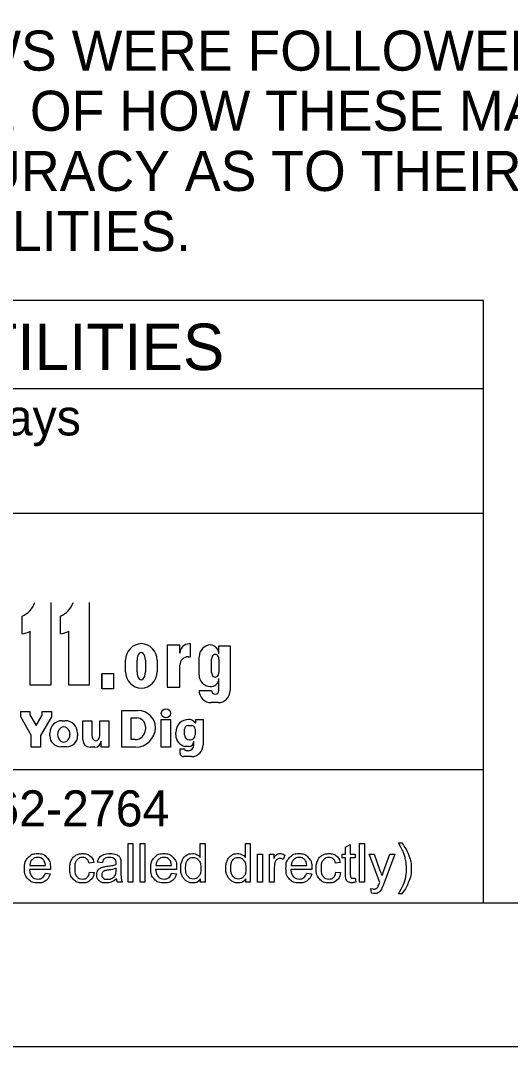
# Model space of a CAD drawing. Extents: x 0 to 34, y 0 to 22.
# Drawn here: x 4.294 to 6.004, y 0 to 3.581 of the extents above; entities that cross this region are included whole.
import ezdxf

# ---------------------------------------------------------------- set-up
doc = ezdxf.new("R2010")
doc.units = 0
for name, color, linetype in [('SH_Border', 7, 'Continuous'), ('SH_Cut_Line', 7, 'Continuous'), ('SH_Data', 7, 'Continuous'), ('SH_Text', 7, 'Continuous')]:
    doc.layers.add(name, color=color, linetype=linetype)

msp = doc.modelspace()

# ---------------------------------------------------------------- linework, layer by layer
at = {"layer": 'SH_Border'}
msp.add_lwpolyline([(1.5, 21.5), (33.5, 21.5), (33.5, 0.5), (1.5, 0.5)], close=True, dxfattribs=at)
at = {"layer": 'SH_Cut_Line'}
msp.add_lwpolyline([(0, 0), (34, 0), (34, 22), (0, 22)], close=True, dxfattribs=at)
at = {"layer": 'SH_Data'}
for p, q in [((5.9103, 2.6037), (2.0853, 2.6037)), ((5.9103, 0.5), (5.9103, 2.6037)), ((2.0853, 2.2963), (5.9103, 2.2963)), ((2.0853, 1.8613), (5.9103, 1.8613)), ((5.9103, 0.9661), (2.0853, 0.9661)), ((5.9103, 0.5), (2.0853, 0.5))]:
    msp.add_line(p, q, dxfattribs=at)
at = {"layer": 'SH_Text'}
for p, q in [((4.3993, 1.5493), (4.3993, 1.2613)), ((4.5333, 1.5493), (4.5333, 1.2613)), ((4.2989, 1.4407), (4.2989, 1.502)), ((4.4328, 1.4407), (4.4328, 1.502)), ((4.3279, 1.2613), (4.3279, 1.4491)), ((4.4619, 1.2613), (4.4619, 1.4491)), ((4.8499, 1.4007), (4.8059, 1.4007)), ((4.8059, 1.4007), (4.8059, 1.254)), ((4.8499, 1.3723), (4.8499, 1.4007)), ((4.8865, 1.4053), (4.8829, 1.4053)), ((4.8865, 1.3605), (4.8865, 1.4053)), ((4.9863, 1.37), (4.9863, 1.3979)), ((4.9863, 1.3979), (5.0255, 1.3979)), ((5.0255, 1.3979), (5.0255, 1.2423)), ((4.6601, 1.3079), (4.6601, 1.3487)), ((4.7006, 1.3072), (4.7006, 1.3487)), ((4.7296, 1.3487), (4.7296, 1.3072)), ((4.7701, 1.3487), (4.7701, 1.3079)), ((4.8499, 1.254), (4.8499, 1.3308)), ((4.8796, 1.3605), (4.8865, 1.3605)), ((4.917, 1.2976), (4.917, 1.3602)), ((4.9606, 1.3059), (4.9606, 1.3519)), ((4.9863, 1.3519), (4.9863, 1.3059)), ((4.5765, 1.3018), (4.5765, 1.2478)), ((4.3993, 1.2613), (4.3279, 1.2613)), ((4.5333, 1.2613), (4.4619, 1.2613)), ((4.8059, 1.254), (4.8499, 1.254)), ((4.9863, 1.2423), (4.9863, 1.284)), ((4.917, 1.2423), (4.9606, 1.2423)), ((4.9834, 1.2002), (4.9591, 1.2002)), ((4.2942, 1.1698), (4.3265, 1.1698)), ((4.2942, 1.1504), (4.2942, 1.1698)), ((4.3314, 1.0866), (4.2942, 1.1504)), ((4.3265, 1.1698), (4.3265, 1.1575)), ((4.3265, 1.1575), (4.3482, 1.1203)), ((4.3482, 1.1203), (4.3691, 1.1562)), ((4.4013, 1.1504), (4.3634, 1.0853)), ((4.3691, 1.1562), (4.3691, 1.1698)), ((4.3691, 1.1698), (4.4013, 1.1698)), ((4.4013, 1.1698), (4.4013, 1.1504)), ((4.6474, 1.173), (4.7035, 1.173)), ((4.6474, 1.0446), (4.6474, 1.173)), ((4.6798, 1.071), (4.6798, 1.1466)), ((4.6798, 1.1466), (4.7, 1.1466)), ((4.4388, 1.1372), (4.4497, 1.1372)), ((4.5109, 1.1372), (4.5422, 1.1372)), ((4.5109, 1.0701), (4.5109, 1.1372)), ((4.5422, 1.1372), (4.5422, 1.0874)), ((4.5705, 1.0859), (4.5705, 1.1372)), ((4.5705, 1.1372), (4.6017, 1.1372)), ((4.6017, 1.1372), (4.6017, 1.0446)), ((4.7294, 1.1173), (4.7294, 1.1066)), ((4.7848, 1.1409), (4.8168, 1.1409)), ((4.7848, 1.0446), (4.7848, 1.1409)), ((4.8168, 1.1409), (4.8168, 1.0446)), ((4.879, 1.1202), (4.8904, 1.1202)), ((4.8974, 1.1359), (4.9051, 1.1299)), ((4.9051, 1.1412), (4.931, 1.1412)), ((4.9051, 1.1299), (4.9051, 1.1412)), ((4.9051, 1.1412), (4.931, 1.1412)), ((4.931, 1.1412), (4.931, 1.0525)), ((4.3314, 1.0446), (4.3314, 1.0866)), ((4.3634, 1.0853), (4.3634, 1.0446)), ((4.3958, 1.0844), (4.3958, 1.0941)), ((4.4928, 1.0941), (4.4928, 1.0844)), ((4.8357, 1.0873), (4.8357, 1.0963)), ((4.8658, 1.088), (4.8658, 1.1071)), ((4.9036, 1.1071), (4.9036, 1.088)), ((4.3634, 1.0446), (4.3314, 1.0446)), ((4.4543, 1.0459), (4.4343, 1.0459)), ((4.5534, 1.0446), (4.5365, 1.0446)), ((4.575, 1.0446), (4.575, 1.0662)), ((4.6017, 1.0446), (4.575, 1.0446)), ((4.6956, 1.0446), (4.6474, 1.0446)), ((4.6938, 1.071), (4.6798, 1.071)), ((4.8168, 1.0446), (4.7848, 1.0446)), ((4.8505, 1.0235), (4.8505, 1.0389)), ((4.8505, 1.0389), (4.8658, 1.0389)), ((4.8807, 1.047), (4.8684, 1.047)), ((4.8862, 1.0706), (4.8832, 1.0706)), ((4.899, 1.0516), (4.899, 1.0655)), ((4.8903, 1.0118), (4.8623, 1.0118)), ((4.8719, 1.0326), (4.8799, 1.0326))]:
    msp.add_line(p, q, dxfattribs=at)
msp.add_lwpolyline([(4.5787, 1.3018), (4.6184, 1.3018), (4.6184, 1.2478), (4.5787, 1.2478)], close=True, dxfattribs=at)
for points in [[(4.6697, 0.573), (4.6697, 0.7082), (4.6862, 0.7082), (4.6862, 0.573), (4.6697, 0.573)], [(4.7116, 0.573), (4.7116, 0.7082), (4.7282, 0.7082), (4.7282, 0.573), (4.7116, 0.573)], [(4.9212, 0.6597), (4.9212, 0.7082), (4.9378, 0.7082), (4.9378, 0.573), (4.9224, 0.573)], [(5.0786, 0.6597), (5.0786, 0.7082), (5.0951, 0.7082), (5.0951, 0.573), (5.0798, 0.573)], [(5.4284, 0.6017), (5.4284, 0.6581), (5.4161, 0.6581), (5.4161, 0.671), (5.4284, 0.671), (5.4284, 0.6952), (5.4449, 0.7052), (5.4449, 0.671), (5.4615, 0.671), (5.4615, 0.6581), (5.4449, 0.6581), (5.4449, 0.6007)], [(5.4774, 0.573), (5.4774, 0.7082), (5.494, 0.7082), (5.494, 0.573), (5.4774, 0.573)], [(5.6131, 0.7104), (5.625, 0.7104)], [(5.1213, 0.573), (5.1213, 0.671), (5.1379, 0.671), (5.1379, 0.573), (5.1213, 0.573)], [(5.1629, 0.573), (5.1629, 0.671), (5.1779, 0.671), (5.1779, 0.6561)], [(5.2161, 0.6678), (5.2103, 0.6525)], [(5.5474, 0.5729), (5.5102, 0.671), (5.5281, 0.671), (5.5485, 0.6144)], [(5.5624, 0.6139), (5.5834, 0.671), (5.6, 0.671), (5.5628, 0.5713)], [(4.3979, 0.6177), (4.3248, 0.6177)], [(4.3257, 0.6313), (4.3804, 0.6313)], [(4.5494, 0.6421), (4.5332, 0.6397)], [(4.5346, 0.6089), (4.5509, 0.6067)], [(4.5786, 0.6408), (4.5623, 0.643)], [(4.6275, 0.6161), (4.6276, 0.6221)], [(4.6443, 0.6362), (4.6443, 0.6141)], [(4.8385, 0.6177), (4.7654, 0.6177)], [(4.7664, 0.6313), (4.8211, 0.6313)], [(5.1795, 0.6243), (5.1795, 0.573), (5.1629, 0.573)], [(5.3105, 0.6177), (5.2375, 0.6177)], [(5.2384, 0.6313), (5.2931, 0.6313)], [(5.4096, 0.6421), (5.3934, 0.6397)], [(5.3949, 0.6089), (5.4112, 0.6067)], [(4.3803, 0.6046), (4.3974, 0.6025)], [(4.6496, 0.573), (4.6323, 0.573)], [(4.8209, 0.6046), (4.838, 0.6025)], [(4.9224, 0.573), (4.9224, 0.5854)], [(5.0798, 0.573), (5.0798, 0.5854)], [(5.2929, 0.6046), (5.3101, 0.6025)], [(5.4615, 0.5878), (5.4639, 0.5732)], [(5.519, 0.5354), (5.5171, 0.551)], [(5.625, 0.5333), (5.6131, 0.5333)]]:
    msp.add_lwpolyline(points, dxfattribs=at)
msp.add_circle((4.8012, 1.1628), 0.016, dxfattribs=at)
for centre, radius, start, end in [((4.2683, 1.5756), 0.0796, 292.5572, 340.7355), ((4.4023, 1.5756), 0.0796, 292.5572, 340.7355), ((4.2917, 1.52), 0.0796, 275.1733, 297.0931), ((4.4256, 1.52), 0.0796, 275.1733, 297.0931), ((4.7177, 1.3487), 0.0576, 92.5886, 180), ((4.7125, 1.3487), 0.0576, 0, 87.4114), ((4.8829, 1.3723), 0.033, 90, 180), ((4.9584, 1.3602), 0.0413, 92.6865, 180), ((4.9547, 1.37), 0.0316, 0, 86.9262), ((4.8796, 1.3308), 0.0297, 90, 180), ((4.7177, 1.3079), 0.0576, 180, 267.4114), ((4.7125, 1.3079), 0.0576, 272.5886, 0), ((4.9587, 1.2976), 0.0417, 180, 265.7132), ((4.9582, 1.284), 0.0281, 264.7825, 0), ((4.9591, 1.2423), 0.0421, 180, 270), ((4.9834, 1.2423), 0.0421, 270, 0), ((4.7, 1.1173), 0.0294, 0, 90), ((4.7035, 1.1116), 0.0614, 0.9944, 90), ((4.4388, 1.0941), 0.043, 90, 180), ((4.4497, 1.0941), 0.043, 0, 90), ((4.6956, 1.1138), 0.0692, 270, 359.0635), ((4.8806, 1.0963), 0.0449, 89.0934, 180), ((4.879, 1.1071), 0.0132, 90, 180), ((4.8818, 1.1158), 0.0254, 52.1415, 91.2046), ((4.8904, 1.1071), 0.0132, 0, 90), ((4.4343, 1.0844), 0.0385, 180, 270), ((4.4543, 1.0844), 0.0385, 270, 0), ((4.6938, 1.1066), 0.0356, 270, 0), ((4.8767, 1.0873), 0.0411, 180, 258.2203), ((4.8832, 1.088), 0.0174, 180, 270), ((4.8862, 1.088), 0.0174, 270, 0), ((4.5365, 1.0701), 0.0255, 180, 270), ((4.5534, 1.0662), 0.0216, 270, 0), ((4.8719, 1.0387), 0.00614, 180, 270), ((4.8799, 1.0516), 0.0191, 270, 0), ((4.8807, 1.0653), 0.0183, 270, 0), ((4.8903, 1.0525), 0.0408, 270, 0), ((4.8623, 1.0235), 0.0118, 180, 270)]:
    msp.add_arc(centre, radius, start, end, dxfattribs=at)
for centre, major_axis, ratio, start_param, end_param in [((4.7151, 1.3487), (0, 0.0262), 0.553236, 4.712389, 7.853982), ((4.9734, 1.3519), (0, 0.0166), 0.777179, 4.712389, 7.853982), ((4.7151, 1.3072), (0, 0.0277), 0.522014, 1.570796, 4.712389), ((4.9734, 1.3059), (0, 0.0166), 0.777179, 1.570796, 4.712389), ((4.9734, 1.2423), (0.0129, 0), 0.959012, 3.141593, 6.283185), ((4.4447, 1.0893), (0, 0.0261), 0.832186, 4.712389, 7.853982), ((4.4447, 1.0893), (0, 0.0272), 0.797287, 1.570796, 4.712389), ((4.5563, 1.088), (-0.001, 0.0208), 0.679042, 1.570796, 4.575961)]:
    msp.add_ellipse(centre, major_axis=major_axis, ratio=ratio, start_param=start_param, end_param=end_param, dxfattribs=at)
for points, degree in [([(5.6131, 0.5333), (5.6406, 0.5775), (5.6406, 0.6218), (5.6406, 0.6392), (5.6367, 0.6562), (5.6336, 0.67), (5.6279, 0.6828), (5.6244, 0.6911), (5.6131, 0.7104)], 3), ([(5.625, 0.7104), (5.6423, 0.6873), (5.6506, 0.664), (5.6577, 0.6439), (5.6577, 0.6219), (5.6577, 0.597), (5.6482, 0.5738), (5.6386, 0.5506), (5.625, 0.5333)], 3), ([(4.3974, 0.6025), (4.3933, 0.5874), (4.3824, 0.5792), (4.3714, 0.5709), (4.3544, 0.5709), (4.3329, 0.5709), (4.3203, 0.5841), (4.3077, 0.5973), (4.3077, 0.6212), (4.3077, 0.6459), (4.3204, 0.6595), (4.3332, 0.6731), (4.3534, 0.6731), (4.3731, 0.6731), (4.3855, 0.6598), (4.3979, 0.6464), (4.3979, 0.6221), (4.3979, 0.6207), (4.3979, 0.6177)], 3), ([(4.3804, 0.6313), (4.3793, 0.6437), (4.3742, 0.6499), (4.3662, 0.6595), (4.3536, 0.6595), (4.3422, 0.6595), (4.3344, 0.6519), (4.3266, 0.6442), (4.3257, 0.6313)], 3), ([(4.5509, 0.6067), (4.5482, 0.5899), (4.5372, 0.5804), (4.5262, 0.5709), (4.5101, 0.5709), (4.49, 0.5709), (4.4778, 0.584), (4.4656, 0.5971), (4.4656, 0.6216), (4.4656, 0.6375), (4.4709, 0.6494), (4.4761, 0.6612), (4.4869, 0.6672), (4.4976, 0.6731), (4.5103, 0.6731), (4.5262, 0.6731), (4.5364, 0.6651), (4.5465, 0.657), (4.5494, 0.6421)], 3), ([(4.5332, 0.6397), (4.5309, 0.6496), (4.525, 0.6545), (4.5192, 0.6595), (4.5109, 0.6595), (4.4984, 0.6595), (4.4905, 0.6505), (4.4827, 0.6416), (4.4827, 0.6221), (4.4827, 0.6023), (4.4903, 0.5934), (4.4978, 0.5845), (4.51, 0.5845), (4.5198, 0.5845), (4.5263, 0.5904), (4.5329, 0.5964), (4.5346, 0.6089)], 3), ([(4.629, 0.5851), (4.6197, 0.5773), (4.6112, 0.5741), (4.6027, 0.5709), (4.5929, 0.5709), (4.5768, 0.5709), (4.5681, 0.5787), (4.5595, 0.5866), (4.5595, 0.5988), (4.5595, 0.606), (4.5627, 0.612), (4.566, 0.6179), (4.5713, 0.6215), (4.5766, 0.6251), (4.5832, 0.6269), (4.5881, 0.6282), (4.598, 0.6294), (4.6181, 0.6318), (4.6275, 0.6351), (4.6276, 0.6385), (4.6276, 0.6395), (4.6276, 0.6496), (4.6229, 0.6538), (4.6166, 0.6594), (4.6041, 0.6594), (4.5924, 0.6594), (4.5868, 0.6553), (4.5813, 0.6512), (4.5786, 0.6408)], 3), ([(4.5623, 0.643), (4.5645, 0.6534), (4.5696, 0.6598), (4.5747, 0.6662), (4.5843, 0.6697), (4.5938, 0.6731), (4.6065, 0.6731), (4.619, 0.6731), (4.6268, 0.6702), (4.6346, 0.6672), (4.6383, 0.6628), (4.642, 0.6583), (4.6435, 0.6515), (4.6443, 0.6472), (4.6443, 0.6362)], 3), ([(4.838, 0.6025), (4.834, 0.5874), (4.823, 0.5792), (4.812, 0.5709), (4.795, 0.5709), (4.7735, 0.5709), (4.7609, 0.5841), (4.7484, 0.5973), (4.7484, 0.6212), (4.7484, 0.6459), (4.7611, 0.6595), (4.7738, 0.6731), (4.7941, 0.6731), (4.8137, 0.6731), (4.8261, 0.6598), (4.8386, 0.6464), (4.8386, 0.6221), (4.8386, 0.6207), (4.8385, 0.6177)], 3), ([(4.8211, 0.6313), (4.82, 0.6437), (4.8148, 0.6499), (4.8069, 0.6595), (4.7942, 0.6595), (4.7828, 0.6595), (4.775, 0.6519), (4.7672, 0.6442), (4.7664, 0.6313)], 3), ([(4.9224, 0.5854), (4.9131, 0.5709), (4.895, 0.5709), (4.8833, 0.5709), (4.8735, 0.5773), (4.8637, 0.5838), (4.8583, 0.5953), (4.8529, 0.6069), (4.8529, 0.6219), (4.8529, 0.6366), (4.8578, 0.6485), (4.8627, 0.6604), (4.8724, 0.6668), (4.8822, 0.6731), (4.8942, 0.6731), (4.9031, 0.6731), (4.91, 0.6694), (4.9169, 0.6657), (4.9212, 0.6597)], 3), ([(4.87, 0.6219), (4.87, 0.6031), (4.8779, 0.5938), (4.8858, 0.5845), (4.8966, 0.5845), (4.9075, 0.5845), (4.9151, 0.5934), (4.9227, 0.6023), (4.9227, 0.6205), (4.9227, 0.6406), (4.915, 0.65), (4.9072, 0.6594), (4.8959, 0.6594), (4.8848, 0.6594), (4.8774, 0.6504), (4.87, 0.6414), (4.87, 0.6219)], 3), ([(5.0798, 0.5854), (5.0705, 0.5709), (5.0524, 0.5709), (5.0407, 0.5709), (5.0309, 0.5773), (5.0211, 0.5838), (5.0157, 0.5953), (5.0103, 0.6069), (5.0103, 0.6219), (5.0103, 0.6366), (5.0152, 0.6485), (5.02, 0.6604), (5.0298, 0.6668), (5.0395, 0.6731), (5.0516, 0.6731), (5.0604, 0.6731), (5.0673, 0.6694), (5.0742, 0.6657), (5.0786, 0.6597)], 3), ([(5.0274, 0.6219), (5.0274, 0.6031), (5.0353, 0.5938), (5.0432, 0.5845), (5.054, 0.5845), (5.0649, 0.5845), (5.0725, 0.5934), (5.0801, 0.6023), (5.0801, 0.6205), (5.0801, 0.6406), (5.0724, 0.65), (5.0646, 0.6594), (5.0533, 0.6594), (5.0422, 0.6594), (5.0348, 0.6504), (5.0274, 0.6414), (5.0274, 0.6219)], 3), ([(5.1779, 0.6561), (5.1836, 0.6665), (5.1884, 0.6698), (5.1932, 0.6731), (5.199, 0.6731), (5.2074, 0.6731), (5.2161, 0.6678)], 3), ([(5.2103, 0.6525), (5.2042, 0.656), (5.1981, 0.656), (5.1927, 0.656), (5.1884, 0.6528), (5.1841, 0.6495), (5.1823, 0.6437), (5.1795, 0.6348), (5.1795, 0.6243)], 3), ([(5.3101, 0.6025), (5.306, 0.5874), (5.295, 0.5792), (5.2841, 0.5709), (5.267, 0.5709), (5.2456, 0.5709), (5.233, 0.5841), (5.2204, 0.5973), (5.2204, 0.6212), (5.2204, 0.6459), (5.2331, 0.6595), (5.2458, 0.6731), (5.2661, 0.6731), (5.2857, 0.6731), (5.2982, 0.6598), (5.3106, 0.6464), (5.3106, 0.6221), (5.3106, 0.6207), (5.3105, 0.6177)], 3), ([(5.2931, 0.6313), (5.292, 0.6437), (5.2868, 0.6499), (5.2789, 0.6595), (5.2663, 0.6595), (5.2548, 0.6595), (5.247, 0.6519), (5.2393, 0.6442), (5.2384, 0.6313)], 3), ([(5.4112, 0.6067), (5.4085, 0.5899), (5.3975, 0.5804), (5.3864, 0.5709), (5.3704, 0.5709), (5.3503, 0.5709), (5.3381, 0.584), (5.3259, 0.5971), (5.3259, 0.6216), (5.3259, 0.6375), (5.3311, 0.6494), (5.3364, 0.6612), (5.3471, 0.6672), (5.3579, 0.6731), (5.3705, 0.6731), (5.3865, 0.6731), (5.3966, 0.6651), (5.4067, 0.657), (5.4096, 0.6421)], 3), ([(5.3934, 0.6397), (5.3911, 0.6496), (5.3853, 0.6545), (5.3794, 0.6595), (5.3711, 0.6595), (5.3586, 0.6595), (5.3508, 0.6505), (5.343, 0.6416), (5.343, 0.6221), (5.343, 0.6023), (5.3505, 0.5934), (5.3581, 0.5845), (5.3703, 0.5845), (5.38, 0.5845), (5.3866, 0.5904), (5.3931, 0.5964), (5.3949, 0.6089)], 3), ([(4.3248, 0.6177), (4.3257, 0.6016), (4.3339, 0.593), (4.3422, 0.5845), (4.3544, 0.5845), (4.3636, 0.5845), (4.37, 0.5893), (4.3765, 0.5941), (4.3803, 0.6046)], 3), ([(4.6276, 0.6221), (4.6186, 0.6185), (4.6005, 0.6159), (4.5903, 0.6144), (4.586, 0.6126), (4.5818, 0.6107), (4.5795, 0.6072), (4.5772, 0.6036), (4.5772, 0.5993), (4.5772, 0.5927), (4.5822, 0.5883), (4.5872, 0.5838), (4.5969, 0.5838), (4.6065, 0.5838), (4.6139, 0.588), (4.6214, 0.5922), (4.6249, 0.5995), (4.6275, 0.6051), (4.6275, 0.6161)], 3), ([(4.6443, 0.6141), (4.6443, 0.5909), (4.6454, 0.5848), (4.6464, 0.5787), (4.6496, 0.573)], 3), ([(4.7654, 0.6177), (4.7664, 0.6016), (4.7746, 0.593), (4.7828, 0.5845), (4.7951, 0.5845), (4.8042, 0.5845), (4.8106, 0.5893), (4.8171, 0.5941), (4.8209, 0.6046)], 3), ([(5.2375, 0.6177), (5.2384, 0.6016), (5.2466, 0.593), (5.2548, 0.5845), (5.2671, 0.5845), (5.2762, 0.5845), (5.2827, 0.5893), (5.2891, 0.5941), (5.2929, 0.6046)], 3), ([(5.5485, 0.6144), (5.5524, 0.6037), (5.5556, 0.5918), (5.5585, 0.603), (5.5624, 0.6139)], 3), ([(4.6323, 0.573), (4.6297, 0.5782), (4.629, 0.5851)], 2), ([(5.4639, 0.5732), (5.4569, 0.5717), (5.4514, 0.5717), (5.4423, 0.5717), (5.4374, 0.5745), (5.4324, 0.5774), (5.4304, 0.5821), (5.4284, 0.5867), (5.4284, 0.6017)], 3), ([(5.4449, 0.6007), (5.4449, 0.5936), (5.4458, 0.5916), (5.4467, 0.5895), (5.4486, 0.5883), (5.4506, 0.5871), (5.4543, 0.5871), (5.457, 0.5871), (5.4615, 0.5878)], 3), ([(5.5171, 0.551), (5.5226, 0.5495), (5.5266, 0.5495), (5.5321, 0.5495), (5.5355, 0.5514), (5.5388, 0.5532), (5.5409, 0.5565), (5.5424, 0.559), (5.5459, 0.5689), (5.5464, 0.5703), (5.5474, 0.5729)], 3), ([(5.5628, 0.5713), (5.5568, 0.5552), (5.5535, 0.5492), (5.5491, 0.541), (5.5433, 0.5372), (5.5376, 0.5334), (5.5297, 0.5334), (5.5249, 0.5334), (5.519, 0.5354)], 3)]:
    msp.add_open_spline(points, degree=degree, dxfattribs=at)

# ---------------------------------------------------------------- texts
at = {"layer": 'SH_Data'}
for s, p in [('DAMAGE PREVENTION LAWS WERE FOLLOWED AND THERE IS  NO DIRECT', (1.7572, 3.406)), ('KNOWLEDGE OR CONTROL OF HOW THESE MARKS WERE PLACED, NOR', (1.7572, 3.196)), ('KNOWLEDGE OF THE ACCURACY AS TO THEIR INTENDED DEPICTION OF', (1.7572, 2.986)), ('SUBSURFACE UTILITY FACILITIES. \xa0', (1.7572, 2.776))]:
    msp.add_text(s, height=0.14, dxfattribs=at).set_placement(p)
at = {"layer": 'SH_Text'}
for s, height, p in [('UNDERGROUND UTILITIES', 0.162, (2.2006, 2.3611)), ('Contact Two Working Days', 0.126, (2.463, 2.1329)), ('OHIO811, 8-1-1, or 1-800-362-2764', 0.126, (2.1253, 0.768))]:
    msp.add_text(s, height=height, dxfattribs=at).set_placement(p)

doc.saveas('drawing.dxf')
